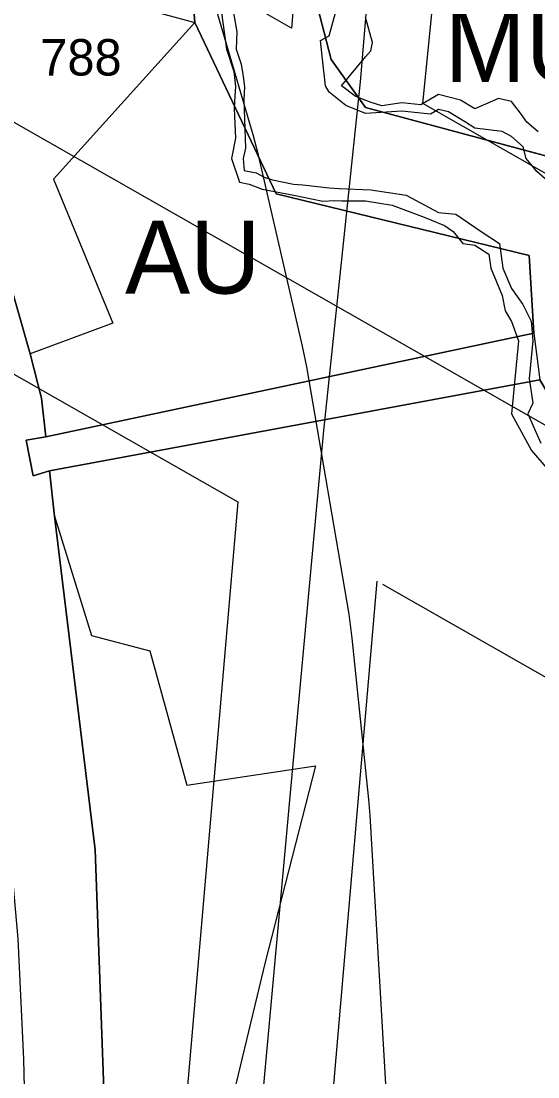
# Model space of a CAD drawing. Extents: x -690419 to -685080, y -987825 to -981190.
# Drawn here: x -686667.2 to -686596.4, y -986400.9 to -986256.1 of the extents above; entities that cross this region are included whole.
import ezdxf

# ---------------------------------------------------------------- set-up
doc = ezdxf.new("R2010")
doc.units = 0
for name, color, linetype in [('BPEJ I-II ochrana', 7, 'Continuous'), ('Elektro VN 35 nadzemní (S)', 7, 'Continuous'), ('Elektro VVN 220 nadzemni (S)', 7, 'Continuous'), ('Katastrální území (S) - hranice', 7, 'Continuous'), ('OP elektro VN (S)', 7, 'Continuous'), ('OP silnic (S)', 7, 'Continuous'), ('Plochy dopravy silniční DS (S)', 7, 'Continuous'), ('Plochy smíšené nezastavěného území všeobecné MU (S)', 7, 'Continuous'), ('Plochy vodní a vodnich toku WT (S)', 7, 'Continuous'), ('Plochy zemědělské všeobecné AU (S)', 7, 'Continuous'), ('Regulacni bloky_ID', 7, 'Continuous'), ('Regulační bloky STABILIZOVANÉ (S)', 7, 'Continuous'), ('Regulační bloky STABILIZOVANÉ (S) TIS', 7, 'Continuous'), ('Regulační kódy STABILIZOVANÉ (S)', 7, 'Continuous'), ('Silnice I třídy (S) - osa', 7, 'Continuous'), ('USES LBK (S)', 7, 'Continuous'), ('USES_ŠRAFY (S)', 7, 'Continuous'), ('Záplavové území aktivní zóna (S)', 7, 'Continuous'), ('Záplavové území Q100 (S)', 7, 'Continuous')]:
    doc.layers.add(name, color=color, linetype=linetype)

msp = doc.modelspace()

# ---------------------------------------------------------------- linework, layer by layer
at = {"layer": 'BPEJ I-II ochrana'}
for p, q in [((-686643.38, -986256.33), (-686662.76, -986277.82)), ((-686632.23, -986279.81), (-686643.38, -986256.33)), ((-686662.76, -986277.82), (-686654.65, -986297.58)), ((-686597.54, -986288.3), (-686632.23, -986279.81)), ((-686596.93, -986298.95), (-686597.54, -986288.3)), ((-686654.65, -986297.58), (-686665.99, -986301.77)), ((-686663.83, -986313.14), (-686596.93, -986298.95)), ((-686665.99, -986301.77), (-686664.4, -986307.82)), ((-686596.08, -986305.34), (-686663.33, -986317.82)), ((-686664.4, -986307.82), (-686663.83, -986313.14)), ((-686663.33, -986317.82), (-686662.66, -986324.04)), ((-686662.66, -986324.04), (-686657.55, -986340.41)), ((-686657.55, -986340.41), (-686649.56, -986342.47)), ((-686649.56, -986342.47), (-686644.48, -986360.93)), ((-686644.48, -986360.93), (-686626.84, -986358.25)), ((-686626.84, -986358.25), (-686633.76, -986385.2)), ((-686633.76, -986385.2), (-686640.61, -986413.7))]:
    msp.add_line(p, q, dxfattribs=at)
at = {"layer": 'Elektro VN 35 nadzemní (S)'}
for points in [[(-686611.26, -986155.55), (-686613.87, -986182.89), (-686620.73, -986264.46), (-686625.76, -986312.28)], [(-686625.76, -986312.29), (-686630.41, -986362.96), (-686639.1, -986458.2), (-686656.15, -986524.8), (-686674.84, -986598.35), (-686694.99, -986677.84), (-686713.19, -986751.11), (-686736.74, -986842.05), (-686762.34, -986942.31), (-686789.09, -987049.22)]]:
    msp.add_lwpolyline(points, dxfattribs=at)
at = {"layer": 'Elektro VVN 220 nadzemni (S)'}
msp.add_lwpolyline([(-686883.06, -986147.5), (-686512.82, -986358.6)], dxfattribs=at)
at = {"layer": 'Katastrální území (S) - hranice'}
for points in [[(-686689.98, -986217.58), (-686665.99, -986301.77), (-686664.4, -986307.82), (-686663.83, -986313.14), (-686666.51, -986313.61), (-686665.56, -986318.5), (-686663.33, -986317.82), (-686662.66, -986324.04), (-686657.08, -986369.79), (-686655.33, -986417.82), (-686658.73, -986468.88), (-686659.13, -986474.94), (-686667.92, -986522.94), (-686676.51, -986555.42), (-686679.91, -986568.27), (-686701.4, -986629.61), (-686711.68, -986654.16), (-686719.78, -986673.5), (-686721.14, -986676.76), (-686721.61, -986676.58), (-686723.39, -986681.23), (-686722.93, -986681.41), (-686724.72, -986686.27), (-686745.98, -986743.92)], [(-686745.98, -986743.92), (-686724.72, -986686.27), (-686722.93, -986681.41), (-686723.39, -986681.23), (-686721.61, -986676.58), (-686721.14, -986676.76), (-686719.78, -986673.5), (-686711.68, -986654.16), (-686701.4, -986629.61), (-686679.91, -986568.27), (-686676.51, -986555.42), (-686667.92, -986522.94), (-686659.13, -986474.94), (-686658.73, -986468.88), (-686655.33, -986417.82), (-686657.08, -986369.79), (-686662.66, -986324.04), (-686663.33, -986317.82), (-686665.56, -986318.5), (-686666.51, -986313.61), (-686663.83, -986313.14), (-686664.4, -986307.82), (-686665.99, -986301.77), (-686689.98, -986217.58)]]:
    msp.add_lwpolyline(points, dxfattribs=at)
at = {"layer": 'OP elektro VN (S)'}
msp.add_line((-686630.15, -986257.1), (-686845.55, -986133.43), dxfattribs=at)
msp.add_lwpolyline([(-686717.27, -986722.57), (-686879.05, -986537.04), (-687014.87, -986381.01), (-687207.62, -986159.36), (-687403.95, -985933.85), (-687488.97, -985836.27), (-687337.77, -985922.59), (-686897.92, -986173.56), (-686637.5, -986322.05), (-686649.13, -986456.85), (-686684.89, -986594.79), (-686717.27, -986722.57)], close=True, dxfattribs=at)
for points in [[(-686622.33, -986164.12), (-686630.15, -986257.1)], [(-685940.35, -986644.99), (-686118.29, -986549.63), (-686307.5, -986448.45), (-686497.59, -986332.75), (-686612.13, -986267.44), (-686602.08, -986166.95), (-686532.25, -986176.25), (-686538.21, -986185.53), (-686551.16, -986207.58)], [(-686700.55, -986741.73), (-686685.87, -986678.26), (-686629.33, -986459.86), (-686618.42, -986332.93)], [(-686617.65, -986333.36), (-686528.05, -986384.45), (-686368.92, -986481.3), (-686546.23, -986678.22), (-686652.77, -986796.5), (-686700.55, -986741.73)]]:
    msp.add_lwpolyline(points, dxfattribs=at)
at = {"layer": 'OP silnic (S)'}
msp.add_lwpolyline([(-686630.59, -986536.21), (-686625.06, -986509.69), (-686624.44, -986506.1), (-686620.67, -986477.82), (-686620.45, -986475.9), (-686618.08, -986450.78), (-686617.86, -986447.06), (-686617.07, -986406.57), (-686617.15, -986402.68), (-686619.35, -986365.09), (-686619.52, -986362.88), (-686621.81, -986340.74), (-686622.26, -986337.45), (-686628.05, -986303.55), (-686628.63, -986300.69), (-686634.69, -986274.52), (-686635.41, -986271.75), (-686647.89, -986229.16)], dxfattribs=at)
at = {"layer": 'Plochy dopravy silniční DS (S)'}
for p, q in [((-686689.98, -986217.58), (-686665.99, -986301.77)), ((-686665.99, -986301.77), (-686664.4, -986307.82)), ((-686664.4, -986307.82), (-686663.83, -986313.14)), ((-686663.83, -986313.14), (-686666.51, -986313.61)), ((-686666.51, -986313.61), (-686665.56, -986318.5)), ((-686665.56, -986318.5), (-686663.33, -986317.82)), ((-686663.33, -986317.82), (-686662.66, -986324.04)), ((-686662.66, -986324.04), (-686657.08, -986369.79)), ((-686657.08, -986369.79), (-686655.33, -986417.82))]:
    msp.add_line(p, q, dxfattribs=at)
at = {"layer": 'Plochy smíšené nezastavěného území všeobecné MU (S)'}
msp.add_lwpolyline([(-686663.73, -986216.26), (-686635.89, -986215.42), (-686594.25, -986225.53), (-686550.46, -986341.17), (-686537.43, -986399.99), (-686549.98, -986397.14), (-686553.27, -986362.5), (-686568.63, -986323.94), (-686584.5, -986302.4), (-686589.89, -986276.07), (-686619.99, -986268), (-686624.7, -986261.38), (-686636.01, -986217.82), (-686664.66, -986238.46)], close=True, dxfattribs=at)
at = {"layer": 'Plochy vodní a vodnich toku WT (S)'}
for points in [[(-686636.01, -986217.82), (-686624.7, -986261.38), (-686619.99, -986268), (-686589.89, -986276.07), (-686584.5, -986302.4), (-686568.63, -986323.94), (-686553.27, -986362.5), (-686549.98, -986397.14), (-686537.43, -986399.99), (-686534.21, -986418.86), (-686547.77, -986439.87), (-686530.23, -986465.49), (-686529.76, -986542.24), (-686532.26, -986564.85), (-686539.48, -986589.87), (-686546.91, -986614.92), (-686584.85, -986665.54), (-686617.44, -986732.54), (-686621.89, -986748.01)], [(-686538.67, -986550.05), (-686537.77, -986479.73), (-686558.79, -986434.27), (-686553.34, -986411.64), (-686557.38, -986401.84), (-686560.8, -986399.5), (-686562.52, -986391.3), (-686570.29, -986348.74), (-686596.08, -986305.34), (-686663.33, -986317.82), (-686665.56, -986318.5), (-686666.51, -986313.61), (-686663.83, -986313.14), (-686596.93, -986298.95), (-686597.54, -986288.3), (-686632.23, -986279.81), (-686643.38, -986256.33), (-686644.68, -986241.46)]]:
    msp.add_lwpolyline(points, dxfattribs=at)
at = {"layer": 'Plochy zemědělské všeobecné AU (S)'}
msp.add_lwpolyline([(-686671.4, -986248.73), (-686644.68, -986241.46), (-686643.38, -986256.33), (-686632.23, -986279.81), (-686597.54, -986288.3), (-686596.93, -986298.95), (-686663.83, -986313.14), (-686664.4, -986307.82), (-686665.99, -986301.77), (-686689.98, -986217.58), (-686678.31, -986216.57)], close=True, dxfattribs=at)
msp.add_lwpolyline([(-686676.51, -986555.42), (-686667.92, -986522.94), (-686659.13, -986474.94), (-686658.73, -986468.88), (-686655.33, -986417.82), (-686657.08, -986369.79), (-686662.66, -986324.04), (-686663.33, -986317.82), (-686596.08, -986305.34), (-686570.29, -986348.74), (-686562.52, -986391.3), (-686560.8, -986399.5), (-686557.38, -986401.84), (-686553.34, -986411.64), (-686558.79, -986434.27), (-686537.77, -986479.73), (-686538.55, -986540.3)], dxfattribs=at)
at = {"layer": 'Regulační bloky STABILIZOVANÉ (S)'}
for p, q in [((-686689.98, -986217.58), (-686665.99, -986301.77)), ((-686665.99, -986301.77), (-686664.4, -986307.82)), ((-686664.4, -986307.82), (-686663.83, -986313.14)), ((-686663.83, -986313.14), (-686666.51, -986313.61)), ((-686666.51, -986313.61), (-686665.56, -986318.5)), ((-686665.56, -986318.5), (-686663.33, -986317.82)), ((-686663.33, -986317.82), (-686662.66, -986324.04)), ((-686662.66, -986324.04), (-686657.08, -986369.79)), ((-686657.08, -986369.79), (-686655.33, -986417.82))]:
    msp.add_line(p, q, dxfattribs=at)
for points in [[(-686663.73, -986216.26), (-686635.89, -986215.42), (-686594.25, -986225.53), (-686550.46, -986341.17), (-686537.43, -986399.99), (-686549.98, -986397.14), (-686553.27, -986362.5), (-686568.63, -986323.94), (-686584.5, -986302.4), (-686589.89, -986276.07), (-686619.99, -986268), (-686624.7, -986261.38), (-686636.01, -986217.82), (-686664.66, -986238.46)], [(-686671.4, -986248.73), (-686644.68, -986241.46), (-686643.38, -986256.33), (-686632.23, -986279.81), (-686597.54, -986288.3), (-686596.93, -986298.95), (-686663.83, -986313.14), (-686664.4, -986307.82), (-686665.99, -986301.77), (-686689.98, -986217.58), (-686678.31, -986216.57)]]:
    msp.add_lwpolyline(points, close=True, dxfattribs=at)
for points in [[(-686636.01, -986217.82), (-686624.7, -986261.38), (-686619.99, -986268), (-686589.89, -986276.07), (-686584.5, -986302.4), (-686568.63, -986323.94), (-686553.27, -986362.5), (-686549.98, -986397.14), (-686537.43, -986399.99), (-686534.21, -986418.86), (-686547.77, -986439.87), (-686530.23, -986465.49), (-686529.76, -986542.24), (-686532.26, -986564.85), (-686539.48, -986589.87), (-686546.91, -986614.92), (-686584.85, -986665.54), (-686617.44, -986732.54), (-686621.89, -986748.01)], [(-686538.67, -986550.05), (-686537.77, -986479.73), (-686558.79, -986434.27), (-686553.34, -986411.64), (-686557.38, -986401.84), (-686560.8, -986399.5), (-686562.52, -986391.3), (-686570.29, -986348.74), (-686596.08, -986305.34), (-686663.33, -986317.82), (-686665.56, -986318.5), (-686666.51, -986313.61), (-686663.83, -986313.14), (-686596.93, -986298.95), (-686597.54, -986288.3), (-686632.23, -986279.81), (-686643.38, -986256.33), (-686644.68, -986241.46)], [(-686676.51, -986555.42), (-686667.92, -986522.94), (-686659.13, -986474.94), (-686658.73, -986468.88), (-686655.33, -986417.82), (-686657.08, -986369.79), (-686662.66, -986324.04), (-686663.33, -986317.82), (-686596.08, -986305.34), (-686570.29, -986348.74), (-686562.52, -986391.3), (-686560.8, -986399.5), (-686557.38, -986401.84), (-686553.34, -986411.64), (-686558.79, -986434.27), (-686537.77, -986479.73), (-686538.55, -986540.3)]]:
    msp.add_lwpolyline(points, dxfattribs=at)
at = {"layer": 'Regulační bloky STABILIZOVANÉ (S) TIS'}
for p, q in [((-686644.68, -986241.46), (-686643.38, -986256.33)), ((-686619.99, -986268), (-686624.7, -986261.38)), ((-686589.89, -986276.07), (-686619.99, -986268)), ((-686596.93, -986298.95), (-686663.83, -986313.14)), ((-686663.33, -986317.82), (-686596.08, -986305.34)), ((-686663.83, -986313.14), (-686666.51, -986313.61)), ((-686666.51, -986313.61), (-686665.56, -986318.5)), ((-686665.56, -986318.5), (-686663.33, -986317.82))]:
    msp.add_line(p, q, dxfattribs=at)
for points in [[(-686624.7, -986261.38), (-686636.01, -986217.82), (-686664.66, -986238.46), (-686663.73, -986216.26)], [(-686643.38, -986256.33), (-686632.23, -986279.81), (-686597.54, -986288.3), (-686596.93, -986298.95)]]:
    msp.add_lwpolyline(points, dxfattribs=at)
at = {"layer": 'Silnice I třídy (S) - osa'}
msp.add_lwpolyline([(-686681.99, -986537.14), (-686679.89, -986528.94), (-686676.6, -986514.13), (-686674.77, -986505), (-686671.83, -986487.38), (-686669.45, -986469.68), (-686667.86, -986452.45), (-686666.83, -986433.96), (-686666.44, -986416.1), (-686666.83, -986398.48), (-686667.63, -986381.97), (-686669.29, -986362.92), (-686671.36, -986345.53), (-686674.14, -986327.83), (-686677.47, -986310.53), (-686681.52, -986292.27), (-686685.8, -986276.16), (-686690.8, -986259.33), (-686696.04, -986242.5)], dxfattribs=at)
at = {"layer": 'USES LBK (S)'}
msp.add_lwpolyline([(-686671.4, -986248.73), (-686643.38, -986256.33), (-686632.23, -986279.81), (-686597.54, -986288.3), (-686596.93, -986298.95), (-686596.08, -986305.34), (-686570.29, -986348.74), (-686560.8, -986399.5), (-686557.38, -986401.84), (-686553.34, -986411.64), (-686558.79, -986434.27), (-686537.77, -986479.73), (-686538.55, -986540.3)], dxfattribs=at)
at = {"layer": 'USES_ŠRAFY (S)'}
msp.add_lwpolyline([(-686671.4, -986248.73), (-686643.38, -986256.33), (-686632.23, -986279.81), (-686597.54, -986288.3), (-686596.93, -986298.95), (-686596.08, -986305.34), (-686570.29, -986348.74), (-686560.8, -986399.5), (-686557.38, -986401.84), (-686553.34, -986411.64), (-686558.79, -986434.27), (-686537.77, -986479.73), (-686538.55, -986540.3)], dxfattribs=at)
at = {"layer": 'Záplavové území aktivní zóna (S)'}
for points in [[(-686638.09, -986255), (-686637.62, -986257.62), (-686637.74, -986260), (-686637.04, -986262.04), (-686636.78, -986263.74), (-686636.61, -986265.14), (-686636.69, -986266.94), (-686636.44, -986273.56), (-686636.76, -986275), (-686636.62, -986276.62), (-686635, -986276.96), (-686633.88, -986277.56), (-686632.76, -986277.9), (-686629.86, -986278.5), (-686628.6, -986278.6), (-686625, -986278.98), (-686623.61, -986279.11), (-686619.26, -986279.26), (-686614.42, -986280), (-686610, -986282.39), (-686607.61, -986282.61), (-686605, -986284.4), (-686604.16, -986285), (-686601.64, -986286.64), (-686601.19, -986290), (-686600, -986292.81), (-686598.44, -986295), (-686597.28, -986297.28), (-686597.07, -986300), (-686597.56, -986305.13), (-686597.05, -986308.53), (-686597.76, -986310), (-686595.98, -986314.02)], [(-686592, -986280.73), (-686596.5, -986276.75), (-686597.99, -986275), (-686598.38, -986273.38), (-686600, -986271.95), (-686601.26, -986271.26), (-686605, -986270.83), (-686606.31, -986270), (-686608.6, -986268.6), (-686610, -986268.24), (-686611.11, -986268.89), (-686615, -986268.5), (-686620, -986268.82), (-686622.69, -986267.69), (-686625, -986265.89), (-686625.48, -986265), (-686625.94, -986260.94), (-686626.19, -986258.81), (-686625, -986258.14), (-686624.11, -986255)]]:
    msp.add_lwpolyline(points, dxfattribs=at)
at = {"layer": 'Záplavové území Q100 (S)'}
for points in [[(-686639.73, -986255), (-686639.07, -986260), (-686638.04, -986263.04), (-686637.82, -986265.09), (-686637.93, -986266.42), (-686638.01, -986268.01), (-686637.95, -986269.24), (-686637.8, -986272.2), (-686638.38, -986275), (-686637.27, -986278.22), (-686635.95, -986278.5), (-686634.18, -986279.18), (-686629.82, -986280), (-686625.83, -986280.83), (-686624.25, -986280.73), (-686623.23, -986280.77), (-686620, -986280.79), (-686616.36, -986281.36), (-686611.97, -986283.03), (-686609.17, -986284.17), (-686607.97, -986285), (-686606.64, -986286.64), (-686605, -986286.84), (-686603.09, -986288.09), (-686602.83, -986290), (-686601.24, -986293.76), (-686600.87, -986295.87), (-686600, -986297.33), (-686599.03, -986300), (-686599.99, -986310.01), (-686597.24, -986315), (-686595, -986317.64)], [(-686596.34, -986271.34), (-686597.86, -986270), (-686598.75, -986268.75), (-686600, -986267.16), (-686601.75, -986266.75), (-686605, -986268.16), (-686606.97, -986266.97), (-686610, -986266.19), (-686612.4, -986267.6), (-686615, -986267.34), (-686617.74, -986267.74), (-686619.21, -986267.28), (-686620.42, -986266.86), (-686621.43, -986266.43), (-686623.27, -986265), (-686620, -986261.05), (-686619.28, -986260.21), (-686619.06, -986259.06), (-686620, -986255.61)]]:
    msp.add_lwpolyline(points, dxfattribs=at)

# ---------------------------------------------------------------- texts
at = {"layer": 'Regulacni bloky_ID'}
msp.add_text('788', height=5, dxfattribs=at).set_placement((-686664.59, -986263.6))
at = {"layer": 'Regulační kódy STABILIZOVANÉ (S)'}
for s, p in [('MU', (-686609.16, -986264.49)), ('AU', (-686652.96, -986293.5))]:
    msp.add_text(s, height=10, dxfattribs=at).set_placement(p)

doc.saveas('drawing.dxf')
